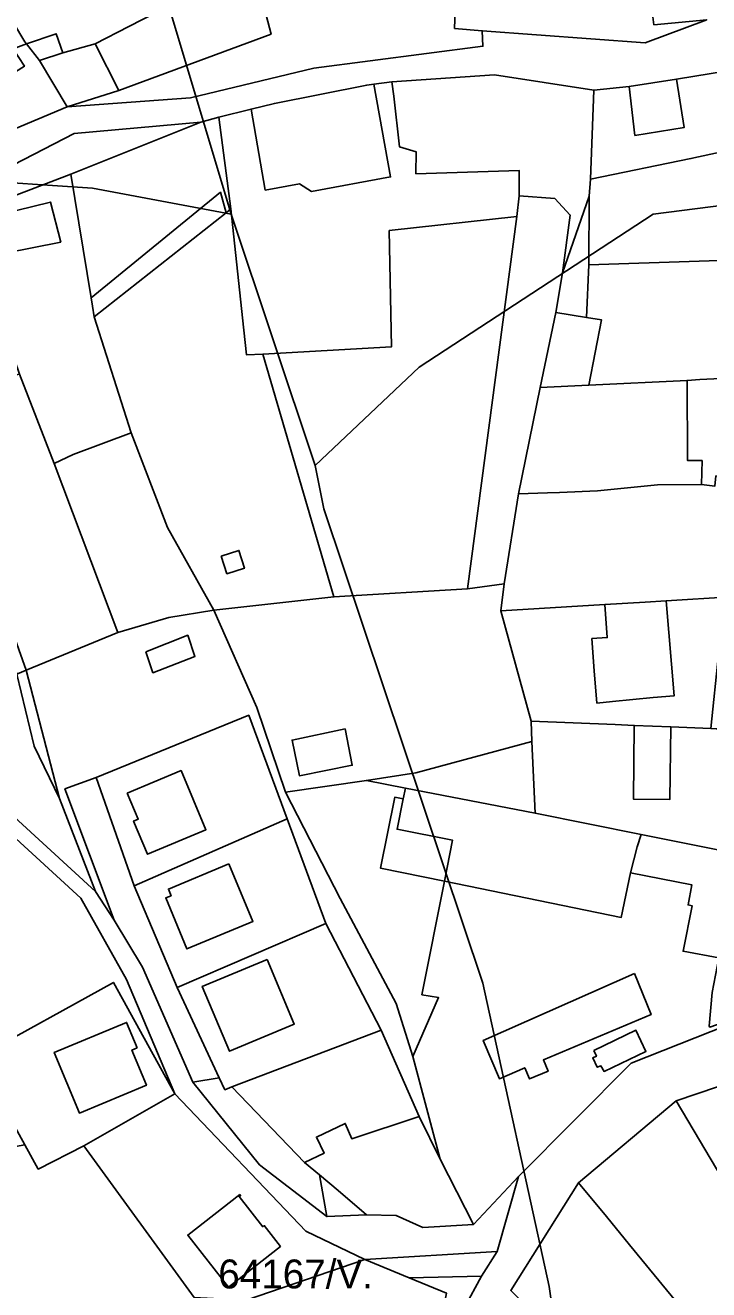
# Model space of a CAD drawing. Extents: x -521261 to -517465, y -1182764 to -1179456.
# Drawn here: x -519625.1 to -519506.9, y -1181340.1 to -1181121.3 of the extents above; entities that cross this region are included whole.
import ezdxf

# ---------------------------------------------------------------- set-up
doc = ezdxf.new("R2010")
doc.units = 0
for name, color, linetype in [('95590013', 7, 'Continuous'), ('95610013', 7, 'Continuous'), ('95640013', 7, 'Continuous'), ('95660013', 7, 'Continuous')]:
    doc.layers.add(name, color=color, linetype=linetype)

msp = doc.modelspace()

# ---------------------------------------------------------------- linework, layer by layer
at = {"layer": '95590013'}
for points in [[(-519674.88, -1181103.81), (-519647.84, -1181093.13), (-519637.5, -1181108.91), (-519638.84, -1181120.93), (-519638.27, -1181122.42), (-519637.08, -1181126.11), (-519637.6, -1181126.45), (-519637.25, -1181127), (-519639.99, -1181128.76), (-519636.18, -1181134.64), (-519633.45, -1181132.89), (-519633.09, -1181133.43), (-519630.98, -1181132.07), (-519630.74, -1181132.46), (-519628.56, -1181131.07), (-519628.81, -1181130.69), (-519625.28, -1181128.43), (-519627.24, -1181125.4), (-519624.89, -1181124.58), (-519622.64, -1181127.41), (-519617.88, -1181135.45), (-519634.27, -1181142.3), (-519654.4, -1181110.38), (-519667.99, -1181115.44)], [(-519619.8, -1181122.82), (-519618.65, -1181126.1), (-519622.64, -1181127.41), (-519624.89, -1181124.58)], [(-519613.06, -1181124.57), (-519608.92, -1181132.65), (-519617.88, -1181135.45), (-519622.64, -1181127.41), (-519618.65, -1181126.1)], [(-519479.2, -1181143.79), (-519471.4, -1181142.42), (-519468.7, -1181160.79), (-519527.63, -1181162.76), (-519527.57, -1181150.92), (-519527.39, -1181147.95), (-519510, -1181144.39), (-519504.41, -1181143.19), (-519504.02, -1181145.34), (-519503.49, -1181148.25), (-519494.56, -1181146.59), (-519492, -1181146.15)], [(-519590.4, -1181153.77), (-519613.21, -1181171.76), (-519613.49, -1181169.91), (-519613.73, -1181168.48), (-519591.36, -1181150.22)], [(-519533.55, -1181151.33), (-519530.87, -1181154.16), (-519532.18, -1181164.17), (-519533.35, -1181171.02), (-519536.05, -1181183.99), (-519539.83, -1181202.37), (-519542.32, -1181217.95), (-519548.64, -1181218.83), (-519540.1, -1181154.44), (-519539.72, -1181150.86)], [(-519589.57, -1181153.12), (-519587.55, -1181171.95), (-519586.84, -1181178.36), (-519584.05, -1181178.25), (-519571.74, -1181220.23), (-519592.5, -1181222.52), (-519600.53, -1181208.19), (-519606.83, -1181191.81), (-519613.21, -1181171.76), (-519590.4, -1181153.77)], [(-519562.17, -1181156.85), (-519540.1, -1181154.44), (-519548.64, -1181218.83), (-519571.74, -1181220.23), (-519584.05, -1181178.25), (-519561.8, -1181176.99)], [(-519640.03, -1181184.44), (-519626.12, -1181181.71), (-519620.14, -1181197.13), (-519609.12, -1181226.38), (-519624.96, -1181232.91), (-519629.76, -1181219.56), (-519631.99, -1181209.71), (-519639.86, -1181194.65), (-519642.47, -1181188.46), (-519643.85, -1181185.19), (-519643.35, -1181185.1), (-519642.81, -1181186.29), (-519639.76, -1181185.15)], [(-519527.64, -1181183.59), (-519510.67, -1181182.78), (-519510.56, -1181196.65), (-519508.06, -1181196.64), (-519508.15, -1181200.77), (-519515.79, -1181200.84), (-519526.18, -1181201.89), (-519532.71, -1181202.17), (-519534.78, -1181202.19), (-519539.83, -1181202.37), (-519536.05, -1181183.99)], [(-519606.83, -1181191.81), (-519600.53, -1181208.19), (-519592.5, -1181222.52), (-519600.29, -1181223.79), (-519609.12, -1181226.38), (-519620.14, -1181197.13), (-519616.83, -1181195.61)], [(-519591.22, -1181213.15), (-519590.26, -1181216.21), (-519587.21, -1181215.25), (-519588.18, -1181212.19)], [(-519591.22, -1181213.15), (-519588.18, -1181212.19), (-519587.21, -1181215.25), (-519590.26, -1181216.21)], [(-519548.64, -1181218.83), (-519542.32, -1181217.95), (-519542.88, -1181222.62), (-519537.61, -1181241.73), (-519537.49, -1181245.2), (-519557.6, -1181250.67), (-519566.11, -1181251.96), (-519580.11, -1181254), (-519585.09, -1181239.37), (-519592.5, -1181222.52), (-519571.74, -1181220.23)], [(-519629.76, -1181219.56), (-519624.96, -1181232.91), (-519626.57, -1181233.57)], [(-519523.09, -1181242.31), (-519519.8, -1181242.45), (-519519.95, -1181255.2), (-519513.67, -1181255.26), (-519513.49, -1181242.69), (-519506.58, -1181242.97), (-519505.59, -1181243.01), (-519493.58, -1181247.04), (-519487.49, -1181248.72), (-519482.42, -1181250.06), (-519485.36, -1181267.89), (-519491.21, -1181266.82), (-519518.59, -1181261.33), (-519536.92, -1181257.61), (-519537.49, -1181245.2), (-519537.61, -1181241.73)], [(-519569.82, -1181243.02), (-519578.99, -1181244.97), (-519577.72, -1181251.16), (-519568.56, -1181249.34)], [(-519609.87, -1181286.89), (-519599.24, -1181306.16), (-519615.01, -1181315.14), (-519622.89, -1181319.19), (-519625.19, -1181315.02), (-519633.51, -1181299.93)], [(-519605.77, -1181298.21), (-519607.59, -1181293.82), (-519620.11, -1181299), (-519615.77, -1181309.49), (-519604.17, -1181304.69), (-519606.69, -1181298.6)], [(-519589.39, -1181304.94), (-519563.57, -1181295.13), (-519556.97, -1181310.11), (-519568.67, -1181313.93), (-519569.78, -1181311.28), (-519574.76, -1181313.66), (-519573.45, -1181316.46), (-519576.81, -1181318.04)], [(-519512.56, -1181307.36), (-519490.95, -1181300.08), (-519480.35, -1181332.79), (-519489.72, -1181336.03), (-519494.57, -1181337.72)], [(-519591.61, -1181303.42), (-519590.59, -1181305.46), (-519589.39, -1181304.94), (-519576.81, -1181318.04), (-519574.24, -1181320.16), (-519572.95, -1181327.41), (-519584.59, -1181318.45), (-519596.14, -1181304.15)], [(-519615.01, -1181315.14), (-519599.24, -1181306.16), (-519576.62, -1181329.91), (-519566.39, -1181334.81), (-519586.91, -1181341.86), (-519595.9, -1181341.38)], [(-519512.56, -1181307.36), (-519494.57, -1181337.72), (-519491.56, -1181342.96), (-519504.06, -1181352.38), (-519509.94, -1181345.27), (-519520.62, -1181332.27), (-519524.62, -1181327.41), (-519529.45, -1181321.54)], [(-519574.24, -1181320.16), (-519571.03, -1181322.89), (-519566.09, -1181327.12), (-519572.95, -1181327.41)], [(-519588.04, -1181323.56), (-519597.01, -1181330.59), (-519589.97, -1181339.59), (-519580.99, -1181332.56), (-519583.8, -1181328.97), (-519584.04, -1181329.15), (-519588.12, -1181323.95), (-519587.89, -1181323.76)], [(-519566.39, -1181334.81), (-519558.73, -1181337.98), (-519552.26, -1181340.67), (-519555.04, -1181353.99), (-519556.37, -1181360.48), (-519560.15, -1181361.95), (-519577.82, -1181369.5), (-519586.91, -1181341.86)]]:
    msp.add_lwpolyline(points, close=True, dxfattribs=at)
at = {"layer": '95610013'}
for points in [[(-519648.79, -1181242.92), (-519640.15, -1181249.77), (-519647.97, -1181244.76), (-519671.01, -1181253.92), (-519663.56, -1181272.64), (-519632.81, -1181259.71), (-519640.15, -1181249.77), (-519615.51, -1181272.35), (-519607.62, -1181286.42), (-519599.24, -1181306.16), (-519609.87, -1181286.89), (-519633.51, -1181299.93), (-519625.19, -1181315.02), (-519654.54, -1181320.25), (-519661.58, -1181324.04), (-519692.36, -1181258.5), (-519671.08, -1181249.99), (-519650.9, -1181241.93)], [(-519622.89, -1181319.19), (-519615.01, -1181315.14), (-519595.9, -1181341.38), (-519586.91, -1181341.86), (-519644.79, -1181360.36), (-519654.93, -1181363.59), (-519667.97, -1181327.48), (-519661.58, -1181324.04), (-519654.54, -1181320.25), (-519625.19, -1181315.02)]]:
    msp.add_lwpolyline(points, close=True, dxfattribs=at)
at = {"layer": '95640013'}
for points in [[(-519627.62, -1181085.06), (-519624.41, -1181083.71), (-519623.65, -1181085.78), (-519626.2, -1181086.49), (-519621.49, -1181101.66), (-519621.1, -1181102.77), (-519617.94, -1181101.92), (-519603.13, -1181097.78), (-519596.61, -1181095.96), (-519593.34, -1181102.43), (-519590.03, -1181104.33), (-519593.54, -1181110.12), (-519598.91, -1181117.4), (-519602.58, -1181119.19), (-519607.21, -1181121.53), (-519613.06, -1181124.57), (-519618.65, -1181126.1), (-519619.8, -1181122.82), (-519624.89, -1181124.58), (-519625.21, -1181124.18), (-519635.08, -1181107.71), (-519644.6, -1181091.87), (-519631.71, -1181086.75)], [(-519646.87, -1181092.77), (-519644.6, -1181091.87), (-519635.08, -1181107.71), (-519625.21, -1181124.18), (-519624.89, -1181124.58), (-519627.24, -1181125.4), (-519629.8, -1181121.43), (-519630.46, -1181121.87), (-519630.73, -1181121.44), (-519633.69, -1181123.35), (-519633.45, -1181123.76), (-519637.08, -1181126.11), (-519638.27, -1181122.42), (-519638.84, -1181120.93), (-519637.5, -1181108.91), (-519647.84, -1181093.13)], [(-519585.59, -1181111.4), (-519582.6, -1181122.9), (-519608.92, -1181132.65), (-519613.06, -1181124.57), (-519607.21, -1181121.53), (-519602.58, -1181119.19), (-519598.91, -1181117.4), (-519593.55, -1181114.79), (-519585.78, -1181110.65)], [(-519517.54, -1181112), (-519517.2, -1181114.75), (-519516.4, -1181121.26), (-519507.26, -1181120.39), (-519517.89, -1181124.37), (-519546.1, -1181122.28), (-519550.86, -1181121.89), (-519550.68, -1181115.46)], [(-519482.04, -1181125.48), (-519474.11, -1181124.5), (-519471.4, -1181142.42), (-519479.2, -1181143.79), (-519492, -1181146.15), (-519494.56, -1181146.59), (-519503.49, -1181148.25), (-519504.02, -1181145.34), (-519504.41, -1181143.19), (-519510, -1181144.39), (-519527.39, -1181147.95), (-519526.81, -1181132.58), (-519520.68, -1181131.92), (-519519.68, -1181140.39), (-519511.15, -1181139.02), (-519512.47, -1181130.64), (-519506.51, -1181129.69), (-519494.21, -1181127.6)], [(-519561.71, -1181131.12), (-519561.37, -1181133.6), (-519560.39, -1181142.37), (-519557.52, -1181143.21), (-519557.55, -1181147.03), (-519539.68, -1181146.47), (-519539.72, -1181150.86), (-519540.1, -1181154.44), (-519562.17, -1181156.85), (-519561.8, -1181176.99), (-519584.05, -1181178.25), (-519586.84, -1181178.36), (-519587.55, -1181171.95), (-519589.57, -1181153.12), (-519591.67, -1181137.22), (-519586.06, -1181135.85), (-519583.63, -1181149.86), (-519577.67, -1181148.74), (-519575.64, -1181150.09), (-519561.93, -1181147.58), (-519564.86, -1181131.53)], [(-519561.71, -1181131.12), (-519543.98, -1181129.89), (-519526.81, -1181132.58), (-519527.39, -1181147.95), (-519527.57, -1181150.92), (-519532.18, -1181164.17), (-519530.87, -1181154.16), (-519533.55, -1181151.33), (-519539.72, -1181150.86), (-519539.68, -1181146.47), (-519557.55, -1181147.03), (-519557.52, -1181143.21), (-519560.39, -1181142.37), (-519561.37, -1181133.6)], [(-519520.68, -1181131.92), (-519512.47, -1181130.64), (-519511.15, -1181139.02), (-519519.68, -1181140.39)], [(-519566.07, -1181131.69), (-519564.86, -1181131.53), (-519561.93, -1181147.58), (-519575.64, -1181150.09), (-519577.67, -1181148.74), (-519583.63, -1181149.86), (-519586.06, -1181135.85), (-519582.04, -1181134.87)], [(-519594.74, -1181138.08), (-519591.67, -1181137.22), (-519589.57, -1181153.12), (-519590.4, -1181153.77), (-519591.36, -1181150.22), (-519613.73, -1181168.48), (-519617.26, -1181147.1)], [(-519594.74, -1181138.08), (-519617.26, -1181147.1), (-519635.82, -1181154.19), (-519642.15, -1181155.58), (-519642.19, -1181153.73), (-519644.72, -1181154.52), (-519616.68, -1181140.04)], [(-519635.82, -1181154.19), (-519617.26, -1181147.1), (-519613.73, -1181168.48), (-519613.49, -1181169.91), (-519613.21, -1181171.76), (-519606.83, -1181191.81), (-519616.83, -1181195.61), (-519620.14, -1181197.13), (-519626.12, -1181181.71), (-519627.7, -1181177.15), (-519633.3, -1181161.67), (-519619, -1181158.86), (-519620.78, -1181151.92), (-519635.41, -1181155.52)], [(-519527.57, -1181150.92), (-519527.63, -1181162.76), (-519528.05, -1181171.88), (-519533.35, -1181171.02), (-519532.18, -1181164.17)], [(-519635.41, -1181155.52), (-519620.78, -1181151.92), (-519619, -1181158.86), (-519633.3, -1181161.67)], [(-519527.63, -1181162.76), (-519468.7, -1181160.79), (-519466.06, -1181180.23), (-519473.45, -1181180.78), (-519498.43, -1181182.05), (-519502.43, -1181182.3), (-519508.46, -1181182.63), (-519510.67, -1181182.78), (-519527.64, -1181183.59), (-519525.45, -1181172.3), (-519528.05, -1181171.88)], [(-519533.35, -1181171.02), (-519528.05, -1181171.88), (-519525.45, -1181172.3), (-519527.64, -1181183.59), (-519536.05, -1181183.99)], [(-519498.43, -1181182.05), (-519473.45, -1181180.78), (-519473.08, -1181193.09), (-519476.69, -1181193.4), (-519476.61, -1181197.21), (-519473.91, -1181200.16), (-519471.21, -1181201.06), (-519463.77, -1181201.39), (-519464.27, -1181205.34), (-519475.56, -1181203.51), (-519482.75, -1181202.56), (-519501.86, -1181199.81), (-519505.67, -1181199.28), (-519505.88, -1181201.07), (-519508.15, -1181200.77), (-519508.06, -1181196.64), (-519510.56, -1181196.65), (-519510.67, -1181182.78), (-519508.46, -1181182.63), (-519502.43, -1181182.3)], [(-519501.86, -1181199.81), (-519482.75, -1181202.56), (-519475.56, -1181203.51), (-519481.26, -1181225.42), (-519487.69, -1181223.63), (-519493.55, -1181222.33), (-519503.16, -1181220.2), (-519514.26, -1181220.87), (-519517.92, -1181221.1), (-519524.86, -1181221.51), (-519542.88, -1181222.62), (-519542.32, -1181217.95), (-519539.83, -1181202.37), (-519534.78, -1181202.19), (-519532.71, -1181202.17), (-519526.18, -1181201.89), (-519515.79, -1181200.84), (-519508.15, -1181200.77), (-519505.88, -1181201.07), (-519505.67, -1181199.28)], [(-519514.26, -1181220.87), (-519503.16, -1181220.2), (-519493.55, -1181222.33), (-519494.91, -1181227.59), (-519504.48, -1181225.46), (-519505.21, -1181230.16), (-519506.58, -1181242.97), (-519513.49, -1181242.69), (-519519.8, -1181242.45), (-519523.09, -1181242.31), (-519537.61, -1181241.73), (-519542.88, -1181222.62), (-519524.86, -1181221.51), (-519524.48, -1181227.24), (-519527.12, -1181227.43), (-519526.75, -1181233.01), (-519526.25, -1181238.57), (-519523.58, -1181238.31), (-519516.55, -1181237.64), (-519512.89, -1181237.3)], [(-519517.92, -1181221.1), (-519514.26, -1181220.87), (-519512.89, -1181237.3), (-519516.55, -1181237.64), (-519523.58, -1181238.31), (-519526.25, -1181238.57), (-519526.75, -1181233.01), (-519527.12, -1181227.43), (-519524.48, -1181227.24), (-519524.86, -1181221.51)], [(-519600.29, -1181223.79), (-519592.5, -1181222.52), (-519585.09, -1181239.37), (-519580.11, -1181254), (-519570.65, -1181272.41), (-519560.98, -1181290.52), (-519558.09, -1181299.71), (-519553.35, -1181317.5), (-519556.97, -1181310.11), (-519563.57, -1181295.13), (-519573.13, -1181276.73), (-519579.84, -1181258.63), (-519586.47, -1181240.69), (-519612.84, -1181251.46), (-519618.27, -1181253.43), (-519609.76, -1181276.13), (-519613, -1181271.17), (-519619.23, -1181255.09), (-519624.96, -1181232.91), (-519609.12, -1181226.38)], [(-519604.29, -1181229.69), (-519603.05, -1181233.35), (-519595.78, -1181230.5), (-519597.02, -1181226.84)], [(-519604.29, -1181229.69), (-519597.02, -1181226.84), (-519595.78, -1181230.5), (-519603.05, -1181233.35)], [(-519626.57, -1181233.57), (-519623.56, -1181246.02), (-519619.23, -1181255.09), (-519613, -1181271.17), (-519643.87, -1181242.87), (-519648.08, -1181240.45)], [(-519626.57, -1181233.57), (-519624.96, -1181232.91), (-519619.23, -1181255.09), (-519623.56, -1181246.02)], [(-519586.47, -1181240.69), (-519579.84, -1181258.63), (-519606.31, -1181270.18), (-519612.84, -1181251.46)], [(-519513.49, -1181242.69), (-519513.67, -1181255.26), (-519519.95, -1181255.2), (-519519.8, -1181242.45)], [(-519569.82, -1181243.02), (-519568.56, -1181249.34), (-519577.72, -1181251.16), (-519578.99, -1181244.97)], [(-519537.49, -1181245.2), (-519536.92, -1181257.61), (-519559.38, -1181253.3), (-519566.11, -1181251.96), (-519557.6, -1181250.67)], [(-519612.84, -1181251.46), (-519606.31, -1181270.18), (-519598.87, -1181287.8), (-519591.61, -1181303.42), (-519596.14, -1181304.15), (-519604.82, -1181284.25), (-519609.76, -1181276.13), (-519618.27, -1181253.43)], [(-519607.48, -1181254.15), (-519605.59, -1181258.66), (-519606.4, -1181259), (-519604, -1181264.73), (-519593.87, -1181260.48), (-519598.18, -1181250.26)], [(-519607.48, -1181254.15), (-519598.18, -1181250.26), (-519593.87, -1181260.48), (-519604, -1181264.73), (-519606.4, -1181259), (-519605.59, -1181258.66)], [(-519559.38, -1181253.3), (-519559.76, -1181255.17), (-519561.22, -1181254.87), (-519563.7, -1181267.11), (-519552.62, -1181269.38), (-519556.51, -1181289.03), (-519553.64, -1181289.53), (-519558.09, -1181299.71), (-519560.98, -1181290.52), (-519570.65, -1181272.41), (-519580.11, -1181254), (-519566.11, -1181251.96)], [(-519559.38, -1181253.3), (-519536.92, -1181257.61), (-519518.59, -1181261.33), (-519519.32, -1181263.46), (-519520.46, -1181267.95), (-519522.05, -1181275.65), (-519552.62, -1181269.38), (-519551.22, -1181262.31), (-519560.81, -1181260.4), (-519559.76, -1181255.17)], [(-519559.76, -1181255.17), (-519560.81, -1181260.4), (-519551.22, -1181262.31), (-519552.62, -1181269.38), (-519563.7, -1181267.11), (-519561.22, -1181254.87)], [(-519606.31, -1181270.18), (-519579.84, -1181258.63), (-519573.13, -1181276.73), (-519598.87, -1181287.8)], [(-519519.32, -1181263.46), (-519518.59, -1181261.33), (-519491.21, -1181266.82), (-519485.36, -1181267.89), (-519488.02, -1181280.85), (-519491.07, -1181287.18), (-519495.45, -1181291.01), (-519497.55, -1181291.4), (-519506.74, -1181294.63), (-519506.84, -1181294.47), (-519506.32, -1181288.64), (-519505.15, -1181282.64), (-519511.35, -1181281.5), (-519509.8, -1181273.63), (-519510.49, -1181273.49), (-519509.81, -1181270.03), (-519520.46, -1181267.95)], [(-519589.91, -1181266.39), (-519585.75, -1181276.36), (-519597.16, -1181281.11), (-519600.82, -1181272.29), (-519599.91, -1181271.91), (-519600.38, -1181270.76)], [(-519589.91, -1181266.39), (-519600.38, -1181270.76), (-519599.91, -1181271.91), (-519600.82, -1181272.29), (-519597.16, -1181281.11), (-519585.75, -1181276.36)], [(-519509.81, -1181270.03), (-519510.49, -1181273.49), (-519509.8, -1181273.63), (-519511.35, -1181281.5), (-519505.15, -1181282.64), (-519506.32, -1181288.64), (-519506.84, -1181294.47), (-519506.74, -1181294.63), (-519497.55, -1181291.4), (-519495.45, -1181291.01), (-519520.31, -1181300.89), (-519539.81, -1181320.48), (-519547.62, -1181328.79), (-519553.35, -1181317.5), (-519558.09, -1181299.71), (-519553.64, -1181289.53), (-519556.51, -1181289.03), (-519552.62, -1181269.38), (-519522.05, -1181275.65), (-519520.46, -1181267.95)], [(-519598.87, -1181287.8), (-519573.13, -1181276.73), (-519563.57, -1181295.13), (-519589.39, -1181304.94), (-519590.59, -1181305.46), (-519591.61, -1181303.42)], [(-519583.28, -1181282.91), (-519594.5, -1181287.58), (-519589.82, -1181298.8), (-519578.61, -1181294.12)], [(-519583.28, -1181282.91), (-519578.61, -1181294.12), (-519589.82, -1181298.8), (-519594.5, -1181287.58)], [(-519519.75, -1181285.33), (-519516.89, -1181292.46), (-519535.52, -1181300.31), (-519534.7, -1181302.25), (-519537.91, -1181303.6), (-519538.73, -1181301.65), (-519543.13, -1181303.55), (-519545.92, -1181296.94)], [(-519519.75, -1181285.33), (-519545.92, -1181296.94), (-519543.13, -1181303.55), (-519538.73, -1181301.65), (-519537.91, -1181303.6), (-519534.7, -1181302.25), (-519535.52, -1181300.31), (-519516.89, -1181292.46)], [(-519605.77, -1181298.21), (-519606.69, -1181298.6), (-519604.17, -1181304.69), (-519615.77, -1181309.49), (-519620.11, -1181299), (-519607.59, -1181293.82)], [(-519526.77, -1181298.65), (-519526.33, -1181299.66), (-519526.97, -1181299.95), (-519526.19, -1181301.58), (-519525.55, -1181301.33), (-519525.01, -1181302.28), (-519517.77, -1181298.83), (-519519.52, -1181295.16)], [(-519526.77, -1181298.65), (-519519.52, -1181295.16), (-519517.77, -1181298.83), (-519525.01, -1181302.28), (-519525.55, -1181301.33), (-519526.19, -1181301.58), (-519526.97, -1181299.95), (-519526.33, -1181299.66)], [(-519574.76, -1181313.66), (-519569.78, -1181311.28), (-519568.67, -1181313.93), (-519556.97, -1181310.11), (-519553.35, -1181317.5), (-519547.62, -1181328.79), (-519556.37, -1181329.29), (-519560.98, -1181327.2), (-519566.09, -1181327.12), (-519571.03, -1181322.89), (-519574.24, -1181320.16), (-519576.81, -1181318.04), (-519573.45, -1181316.46)], [(-519529.45, -1181321.54), (-519524.62, -1181327.41), (-519520.62, -1181332.27), (-519509.94, -1181345.27), (-519519.15, -1181361.65), (-519535.04, -1181346.16), (-519539.22, -1181342.08), (-519541.15, -1181340.2)], [(-519588.04, -1181323.56), (-519587.89, -1181323.76), (-519588.12, -1181323.95), (-519584.04, -1181329.15), (-519583.8, -1181328.97), (-519580.99, -1181332.56), (-519589.97, -1181339.59), (-519597.01, -1181330.59)], [(-519566.39, -1181334.81), (-519543.49, -1181333.42), (-519546.23, -1181337.73), (-519558.73, -1181337.98)], [(-519558.73, -1181337.98), (-519546.23, -1181337.73), (-519555.04, -1181353.99), (-519552.26, -1181340.67)]]:
    msp.add_lwpolyline(points, close=True, dxfattribs=at)
for points in [[(-519550.68, -1181115.46), (-519550.86, -1181121.89), (-519546.1, -1181122.28), (-519545.96, -1181124.96), (-519575.23, -1181128.79), (-519596.57, -1181133.91), (-519617.88, -1181135.45), (-519608.92, -1181132.65), (-519582.6, -1181122.9), (-519585.59, -1181111.4)], [(-519634.27, -1181142.3), (-519617.88, -1181135.45), (-519596.57, -1181133.91), (-519575.23, -1181128.79), (-519545.96, -1181124.96), (-519546.1, -1181122.28), (-519517.89, -1181124.37), (-519507.26, -1181120.39)], [(-519506.51, -1181129.69), (-519512.47, -1181130.64), (-519520.68, -1181131.92), (-519526.81, -1181132.58), (-519543.98, -1181129.89), (-519561.71, -1181131.12), (-519564.86, -1181131.53), (-519566.07, -1181131.69), (-519582.04, -1181134.87), (-519586.06, -1181135.85), (-519591.67, -1181137.22), (-519594.74, -1181138.08), (-519616.68, -1181140.04), (-519644.72, -1181154.52)], [(-519643.87, -1181242.87), (-519613, -1181271.17), (-519609.76, -1181276.13), (-519604.82, -1181284.25), (-519596.14, -1181304.15), (-519584.59, -1181318.45), (-519572.95, -1181327.41), (-519566.09, -1181327.12), (-519560.98, -1181327.2), (-519556.37, -1181329.29), (-519547.62, -1181328.79), (-519539.81, -1181320.48), (-519543.49, -1181333.42), (-519566.39, -1181334.81), (-519576.62, -1181329.91), (-519599.24, -1181306.16), (-519607.62, -1181286.42), (-519615.51, -1181272.35), (-519640.15, -1181249.77)], [(-519555.04, -1181353.99), (-519546.23, -1181337.73), (-519543.49, -1181333.42), (-519539.81, -1181320.48), (-519520.31, -1181300.89), (-519495.45, -1181291.01)], [(-519490.95, -1181300.08), (-519512.56, -1181307.36), (-519529.45, -1181321.54), (-519541.15, -1181340.2)]]:
    msp.add_lwpolyline(points, dxfattribs=at)
at = {"layer": '95660013'}
for points in [[(-519785, -1181088), (-519741.5, -1181060), (-519711, -1181050), (-519636, -1181047), (-519622, -1181070), (-519608, -1181098), (-519600, -1181119), (-519589.5, -1181154), (-519613.5, -1181149.5), (-519636, -1181148), (-519658.72, -1181151.87), (-519672.04, -1181156.22), (-519692.32, -1181164.66), (-519700.84, -1181149.53), (-519735.12, -1181160.39), (-519742.39, -1181165.26), (-519775.16, -1181167.72)], [(-519420, -1181101.5), (-519406, -1181159), (-519429, -1181150), (-519461.5, -1181147), (-519516.5, -1181154), (-519557, -1181180.5), (-519575, -1181197.5), (-519589.5, -1181154), (-519600, -1181119)], [(-519710.5, -1181356), (-519710.5, -1181283.5), (-519707, -1181243.5), (-519697.73, -1181178.01), (-519683.85, -1181172.43), (-519670.38, -1181163.67), (-519655.55, -1181156.71), (-519658.72, -1181151.87), (-519636, -1181148), (-519613.5, -1181149.5), (-519589.5, -1181154), (-519575, -1181197.5), (-519573.5, -1181205), (-519546, -1181287), (-519534.5, -1181339.5), (-519532, -1181357.5)], [(-519428, -1181569.5), (-519443.5, -1181520), (-519453, -1181495), (-519473, -1181470), (-519494, -1181450.5), (-519511.5, -1181423), (-519532, -1181357.5), (-519534.5, -1181339.5), (-519546, -1181287), (-519573.5, -1181205), (-519575, -1181197.5), (-519557, -1181180.5), (-519516.5, -1181154), (-519461.5, -1181147), (-519429, -1181150), (-519406, -1181159), (-519371, -1181269.5), (-519357, -1181319), (-519351.5, -1181351), (-519314, -1181517.5), (-519274, -1181651.5)]]:
    msp.add_lwpolyline(points, dxfattribs=at)

# ---------------------------------------------------------------- texts
msp.add_text('64167/V.', height=5, dxfattribs=at).set_placement((-519591.75, -1181339.83))

doc.saveas('drawing.dxf')
